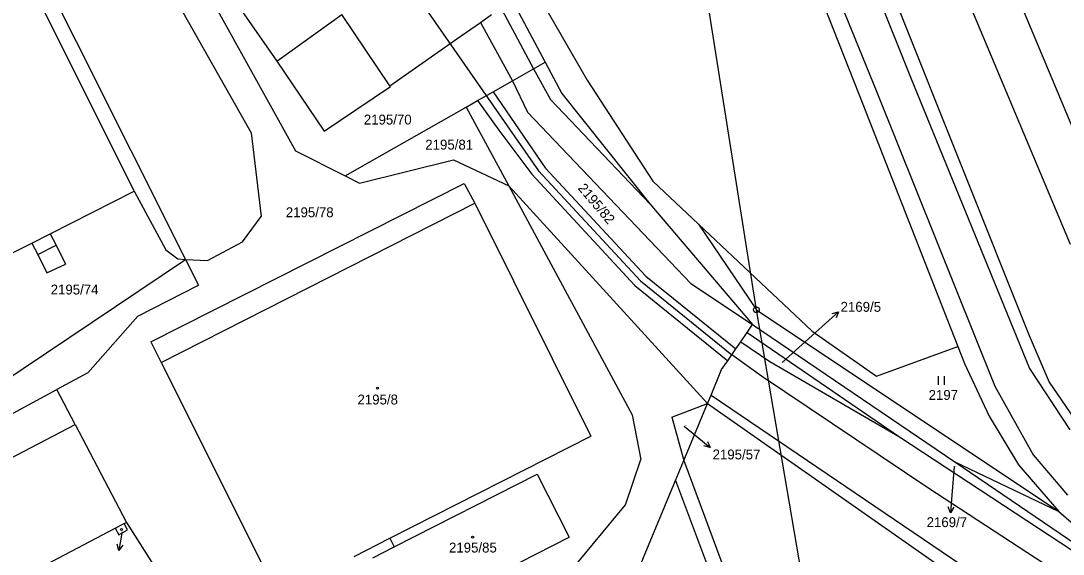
# Model space of a CAD drawing. Extents: x -785744 to -782822, y -1067550 to -1063910.
# Drawn here: x -785002 to -784823, y -1064905.9 to -1064814.4 of the extents above; entities that cross this region are included whole.
import ezdxf

# ---------------------------------------------------------------- set-up
doc = ezdxf.new("R2010")
doc.units = 0
for name, color, linetype in [('Hranice parcel', 7, 'Continuous'), ('Parcelní čísla', 7, 'Continuous'), ('Pop_ČP_popisy', 7, 'Continuous'), ('Poz_předměty', 7, 'Continuous'), ('Vnitřní kresba', 7, 'Continuous'), ('Věcná břemena k části', 7, 'Continuous'), ('Značky budov', 7, 'Continuous'), ('Značky kultur', 7, 'Continuous')]:
    doc.layers.add(name, color=color, linetype=linetype)

msp = doc.modelspace()

# ---------------------------------------------------------------- linework, layer by layer
at = {"layer": 'Hranice parcel'}
for p, q in [((-784927.13, -1064817.49), (-784923.1, -1064814.68)), ((-784923.1, -1064814.68), (-784921.17, -1064813.33)), ((-784923.1, -1064814.68), (-784917.59, -1064824.7)), ((-784929.85, -1064819.4), (-784927.13, -1064817.49)), ((-784938.65, -1064825.55), (-784929.85, -1064819.4)), ((-784985.82, -1064901.51), (-784984.26, -1064900.69)), ((-784984.26, -1064900.69), (-784983.91, -1064900.51)), ((-785021.9, -1064920.34), (-784985.82, -1064901.51))]:
    msp.add_line(p, q, dxfattribs=at)
for points in [[(-785020.7, -1064761.9), (-784973.76, -1064855.35)], [(-785003.29, -1064761.57), (-784962.49, -1064833.61)], [(-785015.52, -1064778.01), (-784982.54, -1064843.66)], [(-784863.25, -1064782.31), (-784828.83, -1064868.44)], [(-784984.19, -1064783.83), (-784958.05, -1064821.33)], [(-784984.19, -1064783.83), (-784954.88, -1064836.71)], [(-784926.54, -1064786.86), (-784904.73, -1064824.58)], [(-784874.09, -1064786.47), (-784858.04, -1064827.11)], [(-784925.99, -1064795.16), (-784911.98, -1064821.51)], [(-784928.03, -1064796.24), (-784913.97, -1064822.64)], [(-784958.05, -1064821.33), (-784949.91, -1064833.35)], [(-784913.97, -1064822.64), (-784911.98, -1064821.51)], [(-784911.98, -1064821.51), (-784909.1, -1064826.91)], [(-784917.59, -1064824.7), (-784913.97, -1064822.64)], [(-784949.91, -1064833.35), (-784938.56, -1064825.68)], [(-784938.65, -1064825.55), (-784938.56, -1064825.68)], [(-784920.91, -1064826.58), (-784917.59, -1064824.7)], [(-784904.73, -1064824.58), (-784893.45, -1064841.94)], [(-784923.58, -1064828.1), (-784920.91, -1064826.58)], [(-784909.1, -1064826.91), (-784894, -1064845.82)], [(-784858.04, -1064827.11), (-784841.06, -1064870.32)], [(-784946.34, -1064841.04), (-784925.51, -1064829.2)], [(-784925.51, -1064829.2), (-784923.58, -1064828.1)], [(-784925.51, -1064829.2), (-784918.22, -1064842.71)], [(-784962.49, -1064833.61), (-784960.74, -1064848.02)], [(-784954.88, -1064836.71), (-784946.34, -1064841.04)], [(-784943.85, -1064842.3), (-784927.69, -1064838.26)], [(-784927.69, -1064838.26), (-784918.22, -1064842.71)], [(-784946.34, -1064841.04), (-784943.85, -1064842.3)], [(-784996.98, -1064850.95), (-784982.54, -1064843.66)], [(-784982.54, -1064843.66), (-784977.13, -1064853.74)], [(-784979.71, -1064869.53), (-784925.87, -1064842.31)], [(-784925.87, -1064842.31), (-784924.04, -1064845.68)], [(-784918.22, -1064842.71), (-784884.07, -1064880.1)], [(-784918.22, -1064842.71), (-784897, -1064882.06)], [(-784893.45, -1064841.94), (-784885.62, -1064849.33)], [(-784924.04, -1064845.68), (-784904.13, -1064885.69)], [(-784894, -1064845.82), (-784876.35, -1064866.55)], [(-784963.96, -1064852.33), (-784960.74, -1064848.02)], [(-784885.62, -1064849.33), (-784875.69, -1064864)], [(-784885.62, -1064849.33), (-784866.12, -1064867.7)], [(-785015.65, -1064860.38), (-785000.15, -1064852.55)], [(-785000.15, -1064852.55), (-784999.14, -1064854.54)], [(-784996.98, -1064850.95), (-784995.98, -1064852.94)], [(-784969.96, -1064855.54), (-784963.96, -1064852.33)], [(-784995.98, -1064852.94), (-784994.35, -1064856.17)], [(-784977.13, -1064853.74), (-784975.04, -1064855.28)], [(-785013.71, -1064882.17), (-784973.76, -1064855.35)], [(-784999.14, -1064854.54), (-784997.55, -1064857.69)], [(-784997.55, -1064857.69), (-784994.35, -1064856.17)], [(-784975.04, -1064855.28), (-784973.76, -1064855.35)], [(-784973.76, -1064855.35), (-784971.52, -1064859.8)], [(-784973.76, -1064855.35), (-784969.96, -1064855.54)], [(-784981.96, -1064865.08), (-784971.52, -1064859.8)], [(-784990.55, -1064874.82), (-784981.96, -1064865.08)], [(-784875.69, -1064864), (-784823.73, -1064898.63)], [(-784877.29, -1064867.93), (-784876.35, -1064866.55)], [(-784876.35, -1064866.55), (-784841.59, -1064890.13)], [(-784878.36, -1064869.48), (-784877.29, -1064867.93)], [(-784877.29, -1064867.93), (-784851.08, -1064885.79)], [(-784866.12, -1064867.7), (-784855.03, -1064875.4)], [(-784828.83, -1064868.44), (-784825.38, -1064876.41)], [(-784979.71, -1064869.53), (-784977.92, -1064873.08)], [(-784879.2, -1064870.71), (-784878.36, -1064869.48)], [(-784878.36, -1064869.48), (-784873.37, -1064872.87)], [(-784855.03, -1064875.4), (-784841.06, -1064870.32)], [(-784841.06, -1064870.32), (-784839.92, -1064873.22)], [(-784880.61, -1064872.77), (-784879.91, -1064871.74)], [(-784879.91, -1064871.74), (-784879.2, -1064870.71)], [(-784977.92, -1064873.08), (-784957.89, -1064913.02)], [(-784881.65, -1064874.28), (-784880.61, -1064872.77)], [(-784873.37, -1064872.87), (-784851.08, -1064885.79)], [(-784839.92, -1064873.22), (-784835.72, -1064882.27)], [(-784990.55, -1064874.82), (-784995.83, -1064877.68)], [(-784883.48, -1064878.68), (-784881.65, -1064874.28)], [(-785046.5, -1064905.09), (-784995.83, -1064877.68)], [(-784992.7, -1064883.67), (-784995.83, -1064877.68)], [(-784825.38, -1064876.41), (-784820.43, -1064883.72)], [(-784884.07, -1064880.1), (-784883.48, -1064878.68)], [(-784883.48, -1064878.68), (-784784.14, -1064945.95)], [(-784890.23, -1064882.41), (-784884.07, -1064880.1)], [(-784888.14, -1064889.88), (-784884.07, -1064880.1)], [(-784884.07, -1064880.1), (-784803.95, -1064936.13)], [(-784897, -1064882.06), (-784895.56, -1064889.69)], [(-784890.23, -1064882.41), (-784888.14, -1064889.88)], [(-784835.72, -1064882.27), (-784830.68, -1064890.64)], [(-785030.69, -1064903.5), (-784992.7, -1064883.67)], [(-784992.7, -1064883.67), (-784983.91, -1064900.51)], [(-784938.64, -1064903.23), (-784904.13, -1064885.69)], [(-784851.08, -1064885.79), (-784819.37, -1064906.65)], [(-784898.15, -1064897.46), (-784895.56, -1064889.69)], [(-784889.57, -1064893.31), (-784888.14, -1064889.88)], [(-784888.14, -1064889.88), (-784876.77, -1064920.52)], [(-784841.59, -1064890.13), (-784823.73, -1064898.63)], [(-784841.59, -1064890.13), (-784809.7, -1064911.76)], [(-784830.68, -1064890.64), (-784823.73, -1064898.63)], [(-784937.89, -1064904.7), (-784913.36, -1064892.22)], [(-784913.36, -1064892.22), (-784907.85, -1064903.04)], [(-784904.22, -1064928.56), (-784889.57, -1064893.31)], [(-784889.57, -1064893.31), (-784879.12, -1064921.21)], [(-784919, -1064922.64), (-784898.15, -1064897.46)], [(-784823.73, -1064898.63), (-784816.19, -1064905.17)], [(-784983.69, -1064901.79), (-784984.26, -1064900.69)], [(-784983.91, -1064900.51), (-784961.59, -1064935.59)], [(-784985.82, -1064901.51), (-784985.21, -1064902.62)], [(-784985.21, -1064902.62), (-784983.69, -1064901.79)], [(-784938.64, -1064903.23), (-784937.89, -1064904.7)], [(-784936.04, -1064917.39), (-784907.85, -1064903.04)], [(-784941.56, -1064906.56), (-784937.89, -1064904.7)]]:
    msp.add_lwpolyline(points, dxfattribs=at)
at = {"layer": 'Pop_ČP_popisy'}
for p, q in [((-784863.81, -1064866.36), (-784861.58, -1064864.35)), ((-784885.94, -1064885.73), (-784883.62, -1064887.63)), ((-784842.09, -1064895.85), (-784842.32, -1064898.84)), ((-784984.66, -1064902.36), (-784985.19, -1064905.31))]:
    msp.add_line(p, q, dxfattribs=at)
for points in [[(-784862.66, -1064864.65), (-784861.58, -1064864.35), (-784861.99, -1064865.39)], [(-784871.27, -1064873.08), (-784863.81, -1064866.36)], [(-784888.11, -1064883.96), (-784885.94, -1064885.73)], [(-784884.08, -1064886.61), (-784883.62, -1064887.63), (-784884.71, -1064887.38)], [(-784841.71, -1064890.92), (-784842.09, -1064895.85)], [(-784841.75, -1064897.88), (-784842.32, -1064898.84), (-784842.74, -1064897.81)], [(-784984.63, -1064902.19), (-784984.66, -1064902.36)], [(-784984.52, -1064904.42), (-784985.19, -1064905.31), (-784985.5, -1064904.24)]]:
    msp.add_lwpolyline(points, dxfattribs=at)
at = {"layer": 'Poz_předměty'}
for points in [[(-784875.69, -1064864), (-784886.75, -1064793.87)], [(-784933.58, -1064810.72), (-784913.11, -1064840.17)], [(-784913.11, -1064840.17), (-784895.61, -1064859.05)], [(-784895.61, -1064859.05), (-784879.91, -1064871.74)], [(-784867.51, -1064911.63), (-784875.69, -1064864)], [(-784874.79, -1064875.39), (-784879.91, -1064871.74)], [(-784846.26, -1064894.55), (-784874.79, -1064875.39)], [(-784770.95, -1064943.74), (-784846.26, -1064894.55)]]:
    msp.add_lwpolyline(points, dxfattribs=at)
msp.add_circle((-784875.69, -1064864), 0.5, dxfattribs=at)
at = {"layer": 'Vnitřní kresba'}
for points in [[(-784865.52, -1064783.36), (-784849.21, -1064824.06)], [(-784871.78, -1064785.44), (-784855, -1064826.66)], [(-784958.05, -1064821.33), (-784946.92, -1064813.31)], [(-784938.65, -1064825.55), (-784946.92, -1064813.31)], [(-784913.97, -1064822.64), (-784911.04, -1064827.94)], [(-784917.59, -1064824.7), (-784915.01, -1064830.07)], [(-784849.21, -1064824.06), (-784828.77, -1064874.06)], [(-784920.91, -1064826.58), (-784911.99, -1064839.62)], [(-784855, -1064826.66), (-784834.72, -1064877.09)], [(-784923.58, -1064828.1), (-784919.93, -1064833.16)], [(-784911.04, -1064827.94), (-784894, -1064845.82)], [(-784915.01, -1064830.07), (-784886.94, -1064859.51)], [(-784919.93, -1064833.16), (-784914.23, -1064840.73)], [(-784911.99, -1064839.62), (-784894.66, -1064858.24)], [(-784914.23, -1064840.73), (-784896.56, -1064859.86)], [(-784977.92, -1064873.08), (-784924.04, -1064845.68)], [(-785000.15, -1064852.55), (-784996.98, -1064850.95)], [(-784999.14, -1064854.54), (-784995.98, -1064852.94)], [(-784894.66, -1064858.24), (-784879.2, -1064870.71)], [(-784886.94, -1064859.51), (-784876.35, -1064866.55)], [(-784896.56, -1064859.86), (-784880.61, -1064872.77)], [(-784828.77, -1064874.06), (-784821.86, -1064884.6)], [(-784834.72, -1064877.09), (-784828.13, -1064888.9)], [(-784828.13, -1064888.9), (-784822.25, -1064895.83)], [(-784944.76, -1064906.34), (-784938.64, -1064903.23)]]:
    msp.add_lwpolyline(points, dxfattribs=at)
at = {"layer": 'Věcná břemena k části'}
for points in [[(-784814.33, -1064849.48), (-784832.88, -1064805.21)], [(-784840.38, -1064808.39), (-784821.81, -1064852.74)]]:
    msp.add_lwpolyline(points, dxfattribs=at)
at = {"layer": 'Značky budov'}
for centre in [(-784940.77, -1064877.45), (-784984.75, -1064901.72), (-784924.43, -1064903.02)]:
    msp.add_circle(centre, 0.175, dxfattribs=at)
at = {"layer": 'Značky kultur'}
for p, q in [((-784844.39, -1064876.91), (-784844.39, -1064875.41)), ((-784843.39, -1064876.91), (-784843.39, -1064875.41))]:
    msp.add_line(p, q, dxfattribs=at)

# ---------------------------------------------------------------- texts
at = {"layer": 'Parcelní čísla'}
for s, height, p in [('2195/70', 1.7, (-784943.12, -1064832.21)), ('2195/81', 1.7, (-784932.56, -1064836.51)), ('2195/78', 1.7, (-784956.52, -1064848.12)), ('2195/74', 1.7, (-784996.91, -1064861.38)), ('2169/5', 0.1, (-784871.27, -1064873.08)), ('2195/8', 1.7, (-784944.21, -1064880.26)), ('2197', 1.7, (-784846.1, -1064879.47)), ('2195/57', 0.1, (-784888.11, -1064883.96)), ('2169/7', 0.1, (-784841.71, -1064890.92)), ('2195/114', 0.1, (-784984.63, -1064902.19)), ('2195/85', 1.7, (-784928.49, -1064905.67))]:
    msp.add_text(s, height=height, dxfattribs=at).set_placement(p)
msp.add_text('2195/82', height=1.7, rotation=310.1753, dxfattribs=at).set_placement((-784906.44, -1064843.19))
at = {"layer": 'Pop_ČP_popisy'}
for s, p in [('2169/5', (-784861.22, -1064864.35)), ('2195/57', (-784883.21, -1064889.69)), ('2169/7', (-784846.44, -1064901.31))]:
    msp.add_text(s, height=1.7, dxfattribs=at).set_placement(p)

doc.saveas('drawing.dxf')
